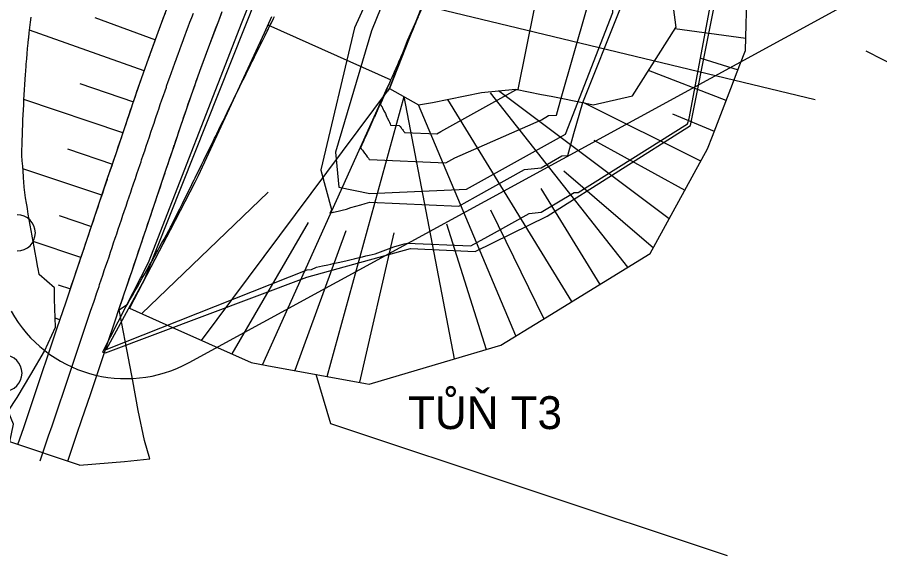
# Model space of a CAD drawing. Extents: x -564037 to -563722, y -1163561 to -1163412.
# Drawn here: x -563903.68 to -563870.9, y -1163513.59 to -1163493.12 of the extents above; entities that cross this region are included whole.
import ezdxf

# ---------------------------------------------------------------- set-up
doc = ezdxf.new("R2010")
doc.units = 0
for name, color, linetype in [('4', 7, 'Continuous'), ('5', 7, 'Continuous'), ('Default', 7, 'Continuous'), ('Line', 7, 'Continuous'), ('Vrstva 2', 7, 'Continuous')]:
    doc.layers.add(name, color=color, linetype=linetype)

msp = doc.modelspace()

# ---------------------------------------------------------------- linework, layer by layer
for p, q in [((-563890.151, -1163481.173), (-563898.85, -1163503.099)), ((-563898.85, -1163503.099), (-563900.295, -1163505.749))]:
    msp.add_line(p, q)
for points in [[(-563900.324, -1163505.882), (-563892.678, -1163503.006), (-563888.735, -1163501.906), (-563886.271, -1163502.018), (-563883.536, -1163500.684), (-563878.095, -1163497.234), (-563876.621, -1163489.849), (-563880.163, -1163485.998), (-563881.977, -1163484.515), (-563883.765, -1163483.269), (-563890.133, -1163481.092), (-563891.974, -1163485.382), (-563895.143, -1163493.304), (-563898.704, -1163502.458), (-563900.439, -1163505.855)], [(-563887.058, -1163484.593), (-563887.855, -1163487.81), (-563890.21, -1163493.633), (-563891.581, -1163498.253), (-563891.461, -1163499.576), (-563890.275, -1163499.82), (-563886.599, -1163499.649), (-563882.84, -1163497.558), (-563881.049, -1163492.941), (-563880.784, -1163487.979), (-563884.81, -1163484.679), (-563886.418, -1163484.198)]]:
    msp.add_lwpolyline(points, close=True)
for points in [[(-563888.153, -1163487.579), (-563890.867, -1163493.518), (-563892.139, -1163498.917), (-563892.146, -1163498.931), (-563891.738, -1163500.429), (-563891.741, -1163500.435), (-563891.799, -1163500.561), (-563891.663, -1163500.529), (-563891.488, -1163500.487), (-563891.327, -1163500.449), (-563891.161, -1163500.409), (-563891.001, -1163500.348), (-563890.81, -1163500.297), (-563890.626, -1163500.247), (-563890.45, -1163500.199), (-563890.281, -1163500.153), (-563886.895, -1163500.296), (-563886.264, -1163499.949), (-563884.401, -1163498.91), (-563883.761, -1163498.848), (-563882.984, -1163498.383), (-563882.755, -1163498.371), (-563882.52, -1163497.536), (-563882.19, -1163496.364), (-563880.778, -1163492.835)], [(-563889.53, -1163495.82), (-563888.841, -1163493.998), (-563888.841, -1163493.998), (-563888.841, -1163493.998), (-563887.797, -1163491.659), (-563887.07, -1163489.251), (-563885.406, -1163487.811), (-563884.336, -1163488.791), (-563884.336, -1163488.791), (-563884.336, -1163488.791), (-563883.356, -1163488.989), (-563882.375, -1163489.186), (-563882.009, -1163489.26), (-563881.395, -1163489.384), (-563880.687, -1163489.526), (-563880.415, -1163489.581), (-563879.434, -1163489.779), (-563879.009, -1163490.8), (-563878.655, -1163493.506)], [(-563886.679, -1163488.563), (-563889.53, -1163495.82), (-563889.609, -1163495.921), (-563889.61, -1163495.921), (-563889.61, -1163495.922), (-563889.703, -1163496.041), (-563889.703, -1163496.041), (-563889.703, -1163496.041), (-563889.703, -1163496.041), (-563889.703, -1163496.041), (-563889.703, -1163496.041), (-563889.703, -1163496.041), (-563889.703, -1163496.041), (-563889.704, -1163496.041), (-563889.704, -1163496.041), (-563889.704, -1163496.041), (-563889.704, -1163496.041), (-563889.704, -1163496.042), (-563889.704, -1163496.042), (-563889.704, -1163496.042), (-563889.704, -1163496.042), (-563889.704, -1163496.042), (-563889.72, -1163496.062), (-563889.762, -1163496.158), (-563889.762, -1163496.159), (-563889.762, -1163496.159), (-563889.784, -1163496.208), (-563889.826, -1163496.303), (-563889.827, -1163496.305), (-563889.848, -1163496.352), (-563889.862, -1163496.385), (-563889.862, -1163496.385), (-563889.878, -1163496.423), (-563889.878, -1163496.423), (-563889.884, -1163496.438), (-563889.845, -1163496.481), (-563889.831, -1163496.497), (-563889.827, -1163496.502), (-563889.809, -1163496.522), (-563889.808, -1163496.523), (-563889.807, -1163496.524), (-563889.807, -1163496.525), (-563889.791, -1163496.589), (-563889.789, -1163496.591), (-563889.788, -1163496.593), (-563889.786, -1163496.595), (-563889.785, -1163496.597), (-563889.784, -1163496.598), (-563889.783, -1163496.6), (-563889.781, -1163496.602), (-563889.78, -1163496.604), (-563889.778, -1163496.606), (-563889.776, -1163496.609), (-563889.775, -1163496.61), (-563889.775, -1163496.611), (-563889.773, -1163496.613), (-563889.771, -1163496.615), (-563889.77, -1163496.618), (-563889.752, -1163496.678), (-563889.686, -1163496.777), (-563889.657, -1163496.853), (-563889.634, -1163496.915), (-563889.625, -1163496.937), (-563889.555, -1163497.058), (-563889.537, -1163497.1), (-563889.511, -1163497.165), (-563889.488, -1163497.222), (-563889.161, -1163497.23), (-563889.125, -1163497.277), (-563889.093, -1163497.319), (-563889.074, -1163497.343), (-563889.064, -1163497.356), (-563889.039, -1163497.39), (-563889.016, -1163497.42), (-563888.995, -1163497.447), (-563888.976, -1163497.472), (-563888.962, -1163497.491), (-563888.962, -1163497.491), (-563888.959, -1163497.494), (-563887.728, -1163497.546), (-563887.583, -1163497.467), (-563884.735, -1163495.88), (-563884.64, -1163495.87), (-563883.396, -1163489.693)], [(-563900.295, -1163505.749), (-563892.658, -1163502.726), (-563892.5, -1163502.714), (-563892.491, -1163502.712), (-563892.306, -1163502.622), (-563892.082, -1163502.572), (-563891.872, -1163502.525), (-563891.762, -1163502.501), (-563891.674, -1163502.481), (-563891.487, -1163502.439), (-563891.31, -1163502.398), (-563891.143, -1163502.36), (-563890.984, -1163502.324), (-563890.87, -1163502.298), (-563890.833, -1163502.289), (-563890.69, -1163502.256), (-563890.554, -1163502.224), (-563890.425, -1163502.194), (-563890.301, -1163502.165), (-563890.187, -1163502.138), (-563890.07, -1163502.109), (-563889.371, -1163501.843), (-563889.235, -1163501.806), (-563889.104, -1163501.771), (-563888.978, -1163501.736), (-563888.857, -1163501.703), (-563886.439, -1163501.806), (-563885.54, -1163501.311), (-563884.217, -1163500.574), (-563883.763, -1163500.529), (-563882.519, -1163499.786), (-563882.357, -1163499.777), (-563878.208, -1163497.166), (-563878.137, -1163496.97), (-563876.837, -1163490)], [(-563901.709, -1163503.594), (-563901.519, -1163503.03), (-563901.312, -1163502.416), (-563901.2, -1163502.083), (-563900.88, -1163501.135), (-563900.561, -1163500.187), (-563900.242, -1163499.24), (-563899.923, -1163498.292), (-563899.604, -1163497.344), (-563899.329, -1163496.528), (-563899.284, -1163496.395), (-563898.956, -1163495.44), (-563898.618, -1163494.488), (-563898.566, -1163494.344), (-563898.27, -1163493.54), (-563897.913, -1163492.595)], [(-563903.651, -1163509.364), (-563903.434, -1163508.717), (-563903.304, -1163508.333), (-563903.114, -1163507.769), (-563902.795, -1163506.821), (-563902.476, -1163505.873), (-563902.157, -1163504.926), (-563901.838, -1163503.978), (-563901.709, -1163503.594), (-563901.613, -1163503.31), (-563901.612, -1163503.306), (-563901.552, -1163503.131), (-563901.519, -1163503.03), (-563901.493, -1163502.955), (-563901.434, -1163502.78), (-563901.375, -1163502.605), (-563901.316, -1163502.429), (-563901.257, -1163502.254), (-563901.2, -1163502.083), (-563901.198, -1163502.079), (-563901.139, -1163501.904), (-563901.08, -1163501.728), (-563901.021, -1163501.553), (-563900.962, -1163501.378), (-563900.903, -1163501.202), (-563900.88, -1163501.135), (-563900.844, -1163501.027), (-563900.785, -1163500.852), (-563900.726, -1163500.676), (-563900.667, -1163500.501), (-563900.608, -1163500.326), (-563900.561, -1163500.187), (-563900.549, -1163500.15), (-563900.49, -1163499.975), (-563900.431, -1163499.8), (-563900.372, -1163499.624), (-563900.313, -1163499.449), (-563900.254, -1163499.274), (-563900.242, -1163499.24), (-563900.194, -1163499.098), (-563900.135, -1163498.923), (-563900.076, -1163498.748), (-563900.017, -1163498.572), (-563899.958, -1163498.397), (-563899.923, -1163498.292), (-563899.899, -1163498.222), (-563899.84, -1163498.046), (-563899.781, -1163497.871), (-563899.722, -1163497.696), (-563899.663, -1163497.52), (-563899.604, -1163497.345), (-563899.604, -1163497.344), (-563899.545, -1163497.17), (-563899.486, -1163496.994), (-563899.427, -1163496.819), (-563899.368, -1163496.644), (-563899.329, -1163496.528), (-563899.309, -1163496.468), (-563899.284, -1163496.395), (-563899.249, -1163496.291), (-563899.188, -1163496.114), (-563899.128, -1163495.937), (-563899.067, -1163495.761), (-563899.006, -1163495.584), (-563898.956, -1163495.44), (-563898.944, -1163495.408), (-563898.882, -1163495.231), (-563898.82, -1163495.055), (-563898.758, -1163494.879), (-563898.695, -1163494.703), (-563898.632, -1163494.527), (-563898.618, -1163494.488), (-563898.568, -1163494.351), (-563898.566, -1163494.344), (-563898.504, -1163494.176), (-563898.44, -1163494), (-563898.376, -1163493.825), (-563898.311, -1163493.65), (-563898.27, -1163493.54), (-563898.246, -1163493.475), (-563898.18, -1163493.3), (-563898.115, -1163493.125), (-563898.048, -1163492.95)], [(-563902.805, -1163509.983), (-563902.486, -1163509.036), (-563902.357, -1163508.652), (-563902.167, -1163508.088), (-563901.848, -1163507.14), (-563901.528, -1163506.193), (-563901.209, -1163505.245), (-563900.89, -1163504.297), (-563900.761, -1163503.913), (-563900.665, -1163503.629), (-563900.664, -1163503.625), (-563900.605, -1163503.45), (-563900.571, -1163503.349), (-563900.546, -1163503.275), (-563900.487, -1163503.099), (-563900.428, -1163502.924), (-563900.369, -1163502.749), (-563900.31, -1163502.573), (-563900.252, -1163502.402), (-563900.251, -1163502.398), (-563900.191, -1163502.223), (-563900.132, -1163502.047), (-563900.073, -1163501.872), (-563900.014, -1163501.697), (-563899.955, -1163501.521), (-563899.933, -1163501.454), (-563899.896, -1163501.346), (-563899.837, -1163501.171), (-563899.778, -1163500.995), (-563899.719, -1163500.82), (-563899.66, -1163500.645), (-563899.613, -1163500.506), (-563899.601, -1163500.469), (-563899.542, -1163500.294), (-563899.483, -1163500.119), (-563899.424, -1163499.943), (-563899.365, -1163499.768), (-563899.306, -1163499.593), (-563899.294, -1163499.559), (-563899.247, -1163499.417), (-563899.188, -1163499.242), (-563899.129, -1163499.067), (-563899.07, -1163498.891), (-563899.011, -1163498.716), (-563898.975, -1163498.611), (-563898.952, -1163498.541), (-563898.893, -1163498.366), (-563898.833, -1163498.19), (-563898.774, -1163498.015), (-563898.715, -1163497.84), (-563898.656, -1163497.664), (-563898.656, -1163497.663), (-563898.597, -1163497.489), (-563898.538, -1163497.314), (-563898.479, -1163497.138), (-563898.42, -1163496.963), (-563898.381, -1163496.847), (-563898.361, -1163496.788), (-563898.337, -1163496.716), (-563898.302, -1163496.612), (-563898.242, -1163496.437), (-563898.182, -1163496.262), (-563898.122, -1163496.087), (-563898.061, -1163495.913), (-563898.012, -1163495.77), (-563898, -1163495.738), (-563897.939, -1163495.563), (-563897.878, -1163495.389), (-563897.816, -1163495.215), (-563897.753, -1163495.04), (-563897.691, -1163494.866), (-563897.677, -1163494.828), (-563897.628, -1163494.692), (-563897.625, -1163494.685), (-563897.565, -1163494.518), (-563897.501, -1163494.345), (-563897.437, -1163494.171), (-563897.373, -1163493.997), (-563897.333, -1163493.889), (-563897.309, -1163493.824), (-563897.244, -1163493.651), (-563897.179, -1163493.478), (-563897.113, -1163493.305), (-563897.048, -1163493.132), (-563896.982, -1163492.959)], [(-563901.756, -1163510.002), (-563901.538, -1163509.355), (-563901.409, -1163508.971), (-563901.219, -1163508.407), (-563900.9, -1163507.459), (-563900.581, -1163506.512), (-563900.262, -1163505.564), (-563899.942, -1163504.616), (-563899.813, -1163504.233), (-563899.717, -1163503.948), (-563899.716, -1163503.944), (-563899.657, -1163503.769), (-563899.623, -1163503.669), (-563899.598, -1163503.594), (-563899.539, -1163503.418), (-563899.48, -1163503.243), (-563899.421, -1163503.068), (-563899.362, -1163502.892), (-563899.304, -1163502.721), (-563899.303, -1163502.717), (-563899.244, -1163502.542), (-563899.185, -1163502.367), (-563899.126, -1163502.191), (-563899.067, -1163502.016), (-563899.008, -1163501.841), (-563898.985, -1163501.773), (-563898.949, -1163501.665), (-563898.89, -1163501.49), (-563898.83, -1163501.315), (-563898.771, -1163501.139), (-563898.712, -1163500.964), (-563898.666, -1163500.826), (-563898.653, -1163500.789), (-563898.594, -1163500.613), (-563898.535, -1163500.438), (-563898.476, -1163500.263), (-563898.417, -1163500.087), (-563898.358, -1163499.912), (-563898.347, -1163499.878), (-563898.299, -1163499.737), (-563898.24, -1163499.561), (-563898.181, -1163499.386), (-563898.122, -1163499.211), (-563898.063, -1163499.035), (-563898.027, -1163498.93), (-563898.004, -1163498.86), (-563897.945, -1163498.685), (-563897.886, -1163498.509), (-563897.827, -1163498.334), (-563897.768, -1163498.159), (-563897.709, -1163497.983), (-563897.708, -1163497.982), (-563897.65, -1163497.808), (-563897.591, -1163497.633), (-563897.532, -1163497.457), (-563897.472, -1163497.282), (-563897.433, -1163497.166), (-563897.414, -1163497.107), (-563897.39, -1163497.036), (-563897.355, -1163496.934), (-563897.296, -1163496.76), (-563897.236, -1163496.587), (-563897.177, -1163496.414), (-563897.117, -1163496.241), (-563897.068, -1163496.1), (-563897.056, -1163496.068), (-563896.996, -1163495.895), (-563896.935, -1163495.723), (-563896.874, -1163495.55), (-563896.812, -1163495.378), (-563896.75, -1163495.205), (-563896.736, -1163495.167), (-563896.688, -1163495.033), (-563896.685, -1163495.026), (-563896.625, -1163494.861), (-563896.562, -1163494.689), (-563896.499, -1163494.517), (-563896.436, -1163494.345), (-563896.396, -1163494.237), (-563896.372, -1163494.173), (-563896.308, -1163494.002), (-563896.243, -1163493.83), (-563896.178, -1163493.659), (-563896.113, -1163493.488), (-563896.048, -1163493.317), (-563896.046, -1163493.311), (-563895.982, -1163493.146), (-563895.916, -1163492.975)], [(-563899.813, -1163504.233), (-563899.623, -1163503.669), (-563899.417, -1163503.055), (-563899.304, -1163502.721), (-563898.985, -1163501.773), (-563898.666, -1163500.826), (-563898.347, -1163499.878), (-563898.027, -1163498.93), (-563897.708, -1163497.982), (-563897.433, -1163497.166), (-563897.39, -1163497.036), (-563897.068, -1163496.1), (-563896.736, -1163495.167), (-563896.685, -1163495.026), (-563896.396, -1163494.237), (-563896.046, -1163493.311), (-563895.888, -1163492.903)], [(-563888.439, -1163493.108), (-563888.499, -1163493.245), (-563888.514, -1163493.28), (-563888.525, -1163493.307), (-563888.54, -1163493.34), (-563888.588, -1163493.451), (-563888.648, -1163493.589), (-563888.663, -1163493.623), (-563888.698, -1163493.705), (-563888.707, -1163493.725), (-563888.731, -1163493.781), (-563888.797, -1163493.933), (-563888.812, -1163493.966), (-563888.853, -1163494.062), (-563888.868, -1163494.095), (-563888.886, -1163494.138), (-563888.93, -1163494.239), (-563888.941, -1163494.264), (-563888.957, -1163494.301), (-563888.961, -1163494.31), (-563888.976, -1163494.345), (-563889.036, -1163494.482), (-563889.095, -1163494.617), (-563889.112, -1163494.654), (-563889.128, -1163494.691), (-563889.187, -1163494.826), (-563889.246, -1163494.958), (-563889.263, -1163494.997), (-563889.322, -1163495.129), (-563889.339, -1163495.169), (-563889.398, -1163495.3), (-563889.416, -1163495.341), (-563889.433, -1163495.381), (-563889.492, -1163495.514), (-563889.492, -1163495.514), (-563889.549, -1163495.643), (-563889.567, -1163495.685), (-563889.624, -1163495.814), (-563889.643, -1163495.857), (-563889.7, -1163495.985), (-563889.719, -1163496.029), (-563889.76, -1163496.121), (-563889.774, -1163496.154), (-563889.779, -1163496.166), (-563889.795, -1163496.203), (-563889.827, -1163496.274), (-563889.847, -1163496.32), (-563889.863, -1163496.355), (-563889.873, -1163496.38), (-563889.877, -1163496.389), (-563889.89, -1163496.418), (-563889.905, -1163496.453), (-563889.95, -1163496.557), (-563889.956, -1163496.571), (-563889.974, -1163496.61), (-563890.028, -1163496.734), (-563890.044, -1163496.77), (-563890.107, -1163496.911), (-563890.121, -1163496.943), (-563890.186, -1163497.088), (-563890.198, -1163497.116), (-563890.265, -1163497.265), (-563890.269, -1163497.275), (-563890.298, -1163497.339), (-563890.304, -1163497.352), (-563890.344, -1163497.442), (-563890.352, -1163497.46), (-563890.423, -1163497.618), (-563890.43, -1163497.632), (-563890.503, -1163497.795), (-563890.507, -1163497.804), (-563890.582, -1163497.972), (-563890.584, -1163497.975), (-563890.633, -1163498.083), (-563890.606, -1163498.118), (-563890.563, -1163498.174), (-563890.538, -1163498.206), (-563890.478, -1163498.284), (-563890.424, -1163498.355), (-563890.376, -1163498.419), (-563890.332, -1163498.478), (-563890.298, -1163498.523), (-563890.297, -1163498.523), (-563890.291, -1163498.531), (-563887.393, -1163498.653), (-563887.052, -1163498.466), (-563883.759, -1163497.017), (-563883.49, -1163496.856), (-563883.188, -1163496.84), (-563883.008, -1163496.199), (-563882.04, -1163492.836)], [(-563902.226, -1163504.902), (-563902.261, -1163503.836), (-563902.265, -1163503.407), (-563902.843, -1163502.896), (-563902.843, -1163502.891), (-563902.884, -1163502.682), (-563902.907, -1163502.563), (-563902.924, -1163502.474), (-563902.964, -1163502.265), (-563903.002, -1163502.057), (-563903.041, -1163501.849), (-563903.078, -1163501.641), (-563903.115, -1163501.438), (-563903.115, -1163501.433), (-563903.152, -1163501.226), (-563903.188, -1163501.018), (-563903.223, -1163500.811), (-563903.258, -1163500.604), (-563903.292, -1163500.398), (-563903.305, -1163500.318), (-563903.326, -1163500.191), (-563903.359, -1163499.985), (-563903.391, -1163499.779), (-563903.411, -1163499.577), (-563903.427, -1163499.376), (-563903.439, -1163499.218), (-563903.442, -1163499.176), (-563903.457, -1163498.976), (-563903.471, -1163498.776), (-563903.485, -1163498.576), (-563903.498, -1163498.376), (-563903.499, -1163498.181), (-563903.498, -1163498.143), (-563903.493, -1163497.987), (-563903.488, -1163497.794), (-563903.482, -1163497.601), (-563903.475, -1163497.408), (-563903.468, -1163497.215), (-563903.463, -1163497.1), (-563903.46, -1163497.023), (-563903.451, -1163496.83), (-563903.442, -1163496.638), (-563903.433, -1163496.446), (-563903.423, -1163496.254), (-563903.413, -1163496.062), (-563903.413, -1163496.061), (-563903.402, -1163495.871), (-563903.39, -1163495.68), (-563903.378, -1163495.489), (-563903.365, -1163495.298), (-563903.357, -1163495.171), (-563903.352, -1163495.104), (-563903.345, -1163495.021), (-563903.336, -1163494.903), (-563903.319, -1163494.703), (-563903.302, -1163494.503), (-563903.283, -1163494.303), (-563903.263, -1163494.103), (-563903.246, -1163493.94), (-563903.242, -1163493.904), (-563903.221, -1163493.704), (-563903.198, -1163493.505), (-563903.174, -1163493.306), (-563903.149, -1163493.108)], [(-563899.803, -1163504.236), (-563899.49, -1163504.025), (-563899.488, -1163504.021), (-563899.394, -1163503.858), (-563899.34, -1163503.764), (-563899.3, -1163503.694), (-563899.206, -1163503.531), (-563899.113, -1163503.367), (-563899.019, -1163503.203), (-563898.926, -1163503.039), (-563898.835, -1163502.879), (-563898.833, -1163502.875), (-563898.74, -1163502.711), (-563898.648, -1163502.547), (-563898.555, -1163502.383), (-563898.463, -1163502.219), (-563898.371, -1163502.055), (-563898.336, -1163501.992), (-563898.28, -1163501.89), (-563898.19, -1163501.725), (-563898.1, -1163501.561), (-563898.01, -1163501.396), (-563897.92, -1163501.231), (-563897.853, -1163501.099), (-563897.835, -1163501.064), (-563897.75, -1163500.897), (-563897.666, -1163500.731), (-563897.582, -1163500.564), (-563897.499, -1163500.397), (-563897.415, -1163500.23), (-563897.399, -1163500.197), (-563897.332, -1163500.062), (-563897.249, -1163499.895), (-563897.166, -1163499.728), (-563897.083, -1163499.561), (-563897, -1163499.393), (-563896.951, -1163499.293), (-563896.918, -1163499.226), (-563896.836, -1163499.058), (-563896.754, -1163498.891), (-563896.671, -1163498.723), (-563896.588, -1163498.556), (-563896.506, -1163498.388), (-563896.505, -1163498.388), (-563896.424, -1163498.221), (-563896.342, -1163498.053), (-563896.26, -1163497.886), (-563896.178, -1163497.718), (-563896.124, -1163497.607), (-563896.097, -1163497.552), (-563896.065, -1163497.484), (-563896.018, -1163497.388), (-563895.938, -1163497.224), (-563895.858, -1163497.061), (-563895.779, -1163496.897), (-563895.699, -1163496.734), (-563895.634, -1163496.601), (-563895.619, -1163496.571), (-563895.54, -1163496.408), (-563895.46, -1163496.245), (-563895.38, -1163496.082), (-563895.3, -1163495.919), (-563895.22, -1163495.756), (-563895.202, -1163495.72), (-563895.14, -1163495.594), (-563895.137, -1163495.587), (-563895.06, -1163495.431), (-563894.98, -1163495.269), (-563894.9, -1163495.106), (-563894.82, -1163494.944), (-563894.77, -1163494.842), (-563894.74, -1163494.782), (-563894.66, -1163494.62), (-563894.58, -1163494.458), (-563894.5, -1163494.296), (-563894.42, -1163494.134), (-563894.339, -1163493.972), (-563894.337, -1163493.967), (-563894.259, -1163493.81), (-563894.179, -1163493.649), (-563894.145, -1163493.581), (-563894.099, -1163493.487), (-563894.019, -1163493.325), (-563893.939, -1163493.164), (-563893.904, -1163493.093)], [(-563889.53, -1163495.82), (-563888.424, -1163496.447), (-563887.893, -1163496.363), (-563886.037, -1163495.972), (-563884.738, -1163495.851), (-563884.738, -1163495.851), (-563884.738, -1163495.851), (-563883.758, -1163496.048), (-563883.391, -1163496.122), (-563882.069, -1163496.388), (-563881.797, -1163496.443), (-563880.3, -1163496.1), (-563878.655, -1163493.506)], [(-563901.311, -1163510.152), (-563899.601, -1163510.007), (-563898.639, -1163509.904), (-563898.845, -1163509.207), (-563899.079, -1163508.073), (-563899.291, -1163506.946), (-563899.504, -1163505.819), (-563899.717, -1163504.692), (-563899.803, -1163504.236)], [(-563901.311, -1163510.152), (-563903.956, -1163509.261), (-563903.825, -1163508.585), (-563904.027, -1163508.089), (-563903.682, -1163507.578), (-563903.161, -1163506.698), (-563902.64, -1163505.818), (-563902.226, -1163504.902)], [(-563876.692, -1163513.593), (-563891.757, -1163508.582), (-563892.317, -1163506.699)]]:
    msp.add_lwpolyline(points)
at = {"layer": '5'}
for p, q in [((-563897.15, -1163506.247), (-563862.812, -1163487.513)), ((-563904.23, -1163488.796), (-563873.359, -1163496.24)), ((-563871.424, -1163494.398), (-563841.172, -1163509.993))]:
    msp.add_line(p, q, dxfattribs=at)
msp.add_arc((-563899.545, -1163501.858), 5, 209.1194, 298.6163, dxfattribs=at)
at = {"layer": 'Default'}
msp.add_lwpolyline([(-563894.011, -1163493.107), (-563894.298, -1163493.726), (-563896.807, -1163499.145), (-563896.925, -1163499.399), (-563897.869, -1163501.213), (-563898.286, -1163502.014), (-563899.415, -1163504.184), (-563898.029, -1163504.804), (-563894.792, -1163506.25), (-563894.189, -1163506.359), (-563890.445, -1163507.038), (-563890.304, -1163507.064), (-563887.435, -1163506.214), (-563885.296, -1163505.58), (-563883.769, -1163504.643), (-563881.393, -1163503.187), (-563879.621, -1163502.1), (-563877.447, -1163498.123), (-563877.26, -1163497.64), (-563876.56, -1163495.83), (-563876.213, -1163494.931), (-563876.002, -1163494.387), (-563875.979, -1163493.391), (-563875.957, -1163492.484)], dxfattribs=at)
at = {"layer": 'Line'}
for p, q in [((-563900.732, -1163493.131), (-563898.43, -1163493.976)), ((-563898.853, -1163495.152), (-563903.21, -1163493.612)), ((-563894.152, -1163493.411), (-563889.486, -1163495.501)), ((-563875.991, -1163493.924), (-563878.691, -1163493.563)), ((-563877.7, -1163494.675), (-563876.286, -1163495.121)), ((-563876.737, -1163496.287), (-563879.693, -1163495.144)), ((-563901.301, -1163495.636), (-563899.263, -1163496.333)), ((-563896.67, -1163505.411), (-563889.53, -1163495.82)), ((-563894.356, -1163506.329), (-563889.596, -1163495.749)), ((-563878.9, -1163500.783), (-563885.388, -1163495.911)), ((-563899.662, -1163497.517), (-563903.423, -1163496.25)), ((-563891.896, -1163506.775), (-563888.977, -1163496.134)), ((-563887.062, -1163506.103), (-563888.977, -1163496.134)), ((-563882.603, -1163503.929), (-563887.316, -1163496.241)), ((-563880.472, -1163502.622), (-563885.697, -1163495.995)), ((-563884.735, -1163505.236), (-563888.424, -1163496.447)), ((-563877.701, -1163498.589), (-563882.149, -1163496.372)), ((-563878.781, -1163496.785), (-563877.188, -1163497.453)), ((-563881.767, -1163497.791), (-563878.301, -1163499.686)), ((-563901.77, -1163498.126), (-563900.061, -1163498.702)), ((-563900.46, -1163499.886), (-563903.464, -1163498.875)), ((-563882.908, -1163498.955), (-563879.5, -1163501.88)), ((-563898.953, -1163504.391), (-563894.136, -1163499.765)), ((-563883.777, -1163499.623), (-563881.537, -1163503.276)), ((-563885.692, -1163500.44), (-563883.669, -1163504.582)), ((-563902.088, -1163500.657), (-563900.859, -1163501.071)), ((-563892.627, -1163500.918), (-563895.529, -1163505.921)), ((-563887.36, -1163500.969), (-563885.863, -1163505.748)), ((-563891.196, -1163501.236), (-563893.126, -1163506.552)), ((-563889.369, -1163501.316), (-563890.666, -1163506.998)), ((-563901.258, -1163502.256), (-563903.078, -1163501.643)), ((-563902.117, -1163503.285), (-563901.657, -1163503.44)), ((-563902.056, -1163504.625), (-563902.237, -1163504.564))]:
    msp.add_line(p, q, dxfattribs=at)
at = {"layer": 'Vrstva 2'}
for centre in [(-563903.678, -1163501.316), (-563904.185, -1163506.649)]:
    msp.add_arc(centre, 0.688, 270, 90, dxfattribs=at)

# ---------------------------------------------------------------- texts
at = {"layer": '4'}
msp.add_text('TŮŇ T3', height=1.25, rotation=360, dxfattribs=at).set_placement((-563888.827, -1163508.776))

doc.saveas('drawing.dxf')
